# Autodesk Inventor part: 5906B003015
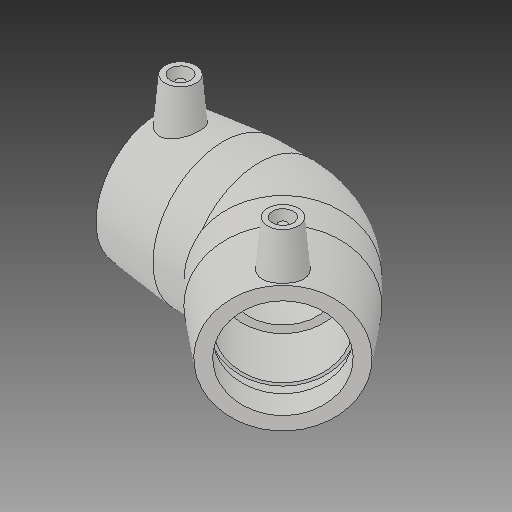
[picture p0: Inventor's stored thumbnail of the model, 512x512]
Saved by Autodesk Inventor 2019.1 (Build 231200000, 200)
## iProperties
Created: 2017-06
Part Number: 5906B003015
Material: Generic
Description: PLASSON 45° ELBOW 1 1/2''
Document SubType Name: Modeling
Designer: KIM
Mass: 55.0731 g
Surface Area: 148.067 cm^2
Volume: 55.0731 cm^3
Density: 1 g/cm^3
Appearance: Default
Author: KIM
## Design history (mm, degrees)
derived "5906B.ipt"
feature "Solid1::5906B.ipt"
tag "TaggingFeature1"
body "Solid1"
other parameters: "d2" = 67.818, "d4" = 30.988, "d5" = 61.0362, "d8" = 168 deg, "d10" = 19.4056, "d11" = 6.46853, "d14" = 17.6296, "d18" = 48.1, "d19" = 3.52592, "d20" = 168 deg, "d22" = 62.39256, "d23" = 67.818, "d24" = 60.52078, "d29" = 51.816, "d30" = 15, "d31" = 49.5808, "d34" = 5 deg, "d35" = 12, "d39" = 0, "d41" = 4, "d42" = 14, "d43" = 0, "d44" = 9.6, "d45" = 4.8, "d46" = 6, "d47" = 0, "d49" = 48.1, "d50" = 40.885, "d51" = 19.4056, "d52" = 48.514, "d54" = 135 deg, "d65" = 48.1, "d67" = 45 deg, "d71" = 135 deg, "d75" = 3.3909, "d82" = 45 deg, "d83" = 48.514, "d84" = 61.0362, "d86" = 30.5181, "d87" = 135 deg, "d88" = 123.952, "d90" = 48.514, "d91" = 0, "d92" = 48.514, "d93" = 0, "d94" = 135 deg, "d95" = 30.26039, "d98" = 123.952, "d99" = 37.1856, "d101" = 3, "d102" = 0, "d103" = 3, "d104" = 0, "d105" = 14.06906, "d106" = 3.51727, "d_" = 48.1, "L_" = 123.952, "L_1" = 48.514, "D_" = 67.818, "A_" = 51.816, "d_2" = 12
